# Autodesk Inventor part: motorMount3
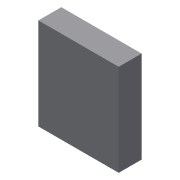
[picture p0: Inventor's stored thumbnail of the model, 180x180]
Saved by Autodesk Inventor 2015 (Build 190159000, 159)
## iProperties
Created: 2016-08
Part Number: motorMount3
Material: EIFS, Exterior Insulation
Document SubType Name: Modeling
Designer: user
Density: 0.023 g/cm^3
Appearance: Gray
Author: user
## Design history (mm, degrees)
sketch "Sketch1"
  geometry: L1 (0, 0)-(-22.225, 0); L2 (-22.225, 0)-(-22.225, 25.4); L3 (-22.225, 25.4)-(0, 25.4); L4 (0, 25.4)-(0, 0)
  constraints: 8 end point, 2 parallel, 1 horizontal, 1 perpendicular
  dimensions: "d0" = 22.225 distance of L2.end L3.end; "d1" = 25.4 distance of L1.end L2.end
extrude "Extrusion1" new body sketch "Sketch1" distance "d2" = 6.35; taper "d3" = 0 deg
body "Solid1"
